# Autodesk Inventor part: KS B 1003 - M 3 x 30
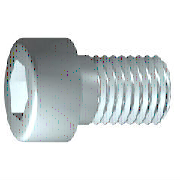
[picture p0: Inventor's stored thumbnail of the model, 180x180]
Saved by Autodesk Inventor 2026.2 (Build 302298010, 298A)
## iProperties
Created: 2025-01
Part Number: KS B 1003 - M 3 x 30
Material: 강철, 연강
Description: 6각머리 태핑 나사
Document SubType Name: Modeling
Standard: KS B 1003
Designer: work
Standards Organization: KS
Language: ko-KR
Size Designation: M 3 x 30
Categories: <MemberInstance><Categories><Category DisplayName="조임쇠" InternalName="e4da775c-781d-43d5-af7c-5136215cf5a6" Mnemonic="FSTN"><Category DisplayName="볼트" InternalN
Density: 7.85 g/cm^3
Appearance: 반연마
IsCustomPart: 1
Author: work
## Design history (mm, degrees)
body "Solid1"
workplane "Work Plane1"
fillet "Fillet2" dims "d30" = 0.1 (= R)
revolve "본체" stored, may be unused: angle "d10" = 90 deg
sketch "스케치2"
  geometry: L1 (0, -3.85)-(0, 3.85) reference; L2 (-3.85, 0)-(3.85, 0) reference; L3 (1.443, 0)-(0.722, -1.25); L4 (0.722, -1.25)-(-0.722, -1.25); L5 (-0.722, -1.25)-(-1.443, 0); L6 (-1.443, 0)-(-0.722, 1.25); L7 (-0.722, 1.25)-(0.722, 1.25); L8 (0.722, 1.25)-(1.443, 0); 2 further points
  constraints: 12 end point, 1 coincident, 1 horizontal alignment, 1 point on line, 12 other
extrude "슬롯" join sketch "스케치2" stored distance "d11" = 10; taper "d12" = 0 deg
fillet "모깎기1" dims "d17" = 0.3 (= RR)
feature "스레드" dims "d13" = 18 (= GEL), "d14" = 0
chamfer "모따기1" distance "d15" = 0.30673 (= -0.5 x SPD + 0.5 x GD); stored, may be unused: second distance "d16" = 0.30673 (= GUL), angle "d27" = 45 deg
sketch "스케치1"
  geometry: L1 (-0.867, 0)-(30, 0); L2 (30, 0)-(30, 1.5); L3 (30, 1.5)-(12, 1.5); L4 (12, 1.5)-(11.693, 1.5); L5 (11.693, 1.5)-(0, 1.5); L6 (0, 1.5)-(0, 2.75); L7 (0, 2.75)-(-3, 2.75); L8 (-3, 2.75)-(-3, 1.443); L9 (-3, 1.443)-(-1.7, 1.443); L10 (-1.7, 1.443)-(-0.867, 0); L11 (-9.6, 0)-(36.6, 0) reference; L12 (0, -0.55)-(0, 3.3) reference; L13 (12, 1.5)-(0, 1.5)
  constraints: 22 end point, 6 parallel, 2 collinear, 2 perpendicular, 1 horizontal, 1 point on line
  dimensions: "d1" = 18 distance from line of L3.end L2 (= GEL); "d2" = 0.30683 distance of L4.end L3.end (computed from GAL); "d3" = 3 distance between parallel lines of L8 L6 (= KOH); "d4" = 1.3 distance of L8.end L9.end (= INTI); "d5" = 60 deg angle of L10 L1; "d6" = 3 diameter of L3 L1 (= GD); "d7" = 3 diameter of L5 L1 (= BDM); "d8" = 2.88675 diameter of L9 L1 (= 1.1547 x SW); "d9" = 5.5 diameter of L7 L1 (= KOD); "d26" = 30 distance between parallel lines of L12 L2 (= NLG)
other parameters: "GD" = 3 (= NND) [user parameter; used in 2 equation terms], "NLG" = 30 [user parameter; used in 1 equation term], "GEL" = 18 [user parameter; used in 2 equation terms], "KOD" = 5.5 [user parameter; used in 1 equation term], "KOH" = 3 [user parameter; used in 1 equation term], "INTI" = 1.3 [user parameter; used in 1 equation term], "GAL" = 0.30673 (= 0.61345 x PTC) [user parameter; used in 1 equation term], "GUL" = 0.30673 (= 0.61345 x PTC) [user parameter; used in 1 equation term], "BDM" = 3 (= NND) [user parameter; used in 1 equation term], "SW" = 2.5 [user parameter; used in 2 equation terms], "RR" = 0.3 [user parameter; used in 1 equation term], "SPD" = 2.38655 (= NND - 1.2269 x PTC) [user parameter; used in 1 equation term], "d19" = 0, "d28" = 0, "d29" = 0, "R" = 0.1 [user parameter; used in 1 equation term], "PHH" = 0.1 [user parameter], "GD1" = 2.38655 (= THREADDIA - 1.2269 x PTC) [user parameter], "THREADDIA" = 3 [user parameter; used in 1 equation term], "FAWI" = 45 deg [user parameter], "PTC" = 0.5 [user parameter; used in 5 equation terms], "NND" = 3 [user parameter; used in 3 equation terms], "TOA" = 30 deg [user parameter], "E0" = 2.8875 (= 1.155 x SW) [user parameter]
